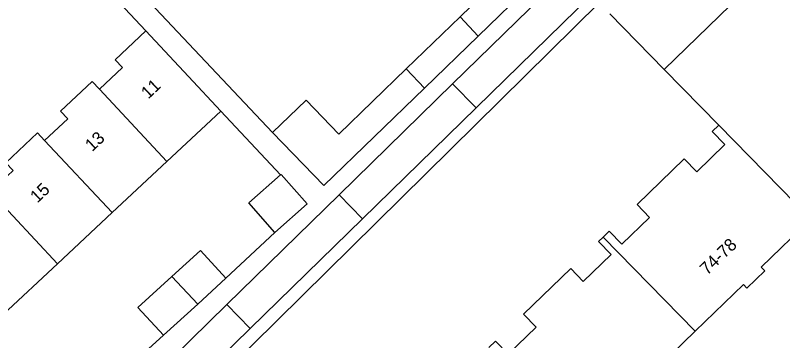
# Model space of a CAD drawing. Extents: x 161882 to 162509, y 381687 to 382379.
# Drawn here: x 162409.8 to 162471.3, y 381812.8 to 381838.9 of the extents above; entities that cross this region are included whole.
import ezdxf

# ---------------------------------------------------------------- set-up
doc = ezdxf.new("R2010")
doc.units = 0
for name, color, linetype in [('IMGEO_Pand', 7, 'Continuous'), ('IMGEO_Pand_nummerreeks', 7, 'Continuous'), ('IMGEO_Rijbaan_lokaal_open', 7, 'Continuous'), ('IMGEO_Voetpad_open', 7, 'Continuous')]:
    doc.layers.add(name, color=color, linetype=linetype)

msp = doc.modelspace()

# ---------------------------------------------------------------- linework, layer by layer
at = {"layer": 'IMGEO_Pand'}
for points in [[(162461.809, 381834.525), (162468.874, 381841.412), (162472.454, 381844.902), (162474.369, 381842.947)], [(162445.46, 381838.744), (162449.764, 381842.916)], [(162444.862, 381833.372), (162454.078, 381842.393), (162455.959, 381840.477), (162446.742, 381831.455)], [(162451.213, 381841.37), (162446.909, 381837.198)], [(162441.156, 381834.572), (162445.46, 381838.744)], [(162446.909, 381837.198), (162445.46, 381838.744)], [(162416.575, 381832.94), (162418.422, 381834.667), (162417.831, 381835.299), (162420.305, 381837.611)], [(162426.31, 381831.186), (162423.719, 381833.958), (162420.305, 381837.611)], [(162446.909, 381837.198), (162442.605, 381833.026)], [(162430.442, 381829.459), (162433.129, 381832.063), (162435.763, 381829.345), (162441.156, 381834.572)], [(162441.156, 381834.572), (162442.605, 381833.026)], [(162461.809, 381834.525), (162466.185, 381830.057)], [(162412.188, 381828.836), (162414.043, 381830.57), (162413.465, 381831.188), (162415.999, 381833.556), (162416.575, 381832.94)], [(162435.772, 381824.472), (162444.862, 381833.372)], [(162444.862, 381833.372), (162446.742, 381831.455)], [(162416.575, 381832.94), (162421.988, 381827.147)], [(162442.605, 381833.026), (162434.551, 381825.22), (162430.442, 381829.459)], [(162446.742, 381831.455), (162437.651, 381822.555)], [(162426.31, 381831.186), (162421.988, 381827.147)], [(162466.185, 381830.057), (162465.65, 381829.539), (162466.659, 381828.498), (162464.418, 381826.327), (162463.409, 381827.368), (162459.63, 381823.708), (162460.639, 381822.667), (162458.413, 381820.511), (162457.404, 381821.552), (162456.915, 381821.079)], [(162473.56, 381822.527), (162466.185, 381830.057)], [(162412.188, 381828.836), (162411.632, 381829.429), (162409.083, 381827.047), (162409.665, 381826.424), (162407.83, 381824.709)], [(162417.6, 381823.046), (162412.188, 381828.836)], [(162421.988, 381827.147), (162417.6, 381823.046)], [(162430.632, 381821.461), (162428.548, 381823.828), (162431.094, 381826.068)], [(162431.094, 381826.068), (162431.145, 381826.113), (162433.228, 381823.746), (162430.632, 381821.461)], [(162407.83, 381824.709), (162413.215, 381818.948)], [(162426.783, 381815.673), (162435.772, 381824.472)], [(162437.651, 381822.555), (162435.772, 381824.472)], [(162413.215, 381818.948), (162417.6, 381823.046)], [(162437.651, 381822.555), (162428.663, 381813.756)], [(162464.294, 381813.553), (162468.154, 381817.292), (162468.433, 381817.005), (162469.863, 381818.389), (162469.584, 381818.676), (162473.56, 381822.527)], [(162456.915, 381821.079), (162456.549, 381820.724), (162457.558, 381819.683), (162455.331, 381817.526), (162454.322, 381818.567), (162450.544, 381814.907), (162451.553, 381813.866), (162449.319, 381811.703), (162448.31, 381812.744), (162447.776, 381812.227)], [(162456.915, 381821.079), (162464.294, 381813.553)], [(162422.384, 381817.928), (162424.674, 381820.019), (162426.715, 381817.784)], [(162413.215, 381818.948), (162408.862, 381814.879)], [(162421.709, 381813.214), (162419.669, 381815.448), (162422.384, 381817.928)], [(162422.384, 381817.928), (162424.451, 381815.717)], [(162426.715, 381817.784), (162424.451, 381815.717)], [(162408.087, 381797.371), (162426.783, 381815.673)], [(162424.451, 381815.717), (162421.709, 381813.214)], [(162426.783, 381815.673), (162428.663, 381813.756)], [(162428.663, 381813.756), (162409.777, 381795.269)], [(162455.154, 381804.701), (162458.924, 381808.352), (162459.203, 381808.065), (162460.711, 381809.526), (162460.432, 381809.813), (162464.294, 381813.553)]]:
    msp.add_lwpolyline(points, dxfattribs=at)
at = {"layer": 'IMGEO_Rijbaan_lokaal_open'}
msp.add_lwpolyline([(162457.462, 381838.965), (162461.809, 381834.525)], dxfattribs=at)
at = {"layer": 'IMGEO_Voetpad_open'}
for points in [[(162430.442, 381829.459), (162415.713, 381845.109)], [(162420.305, 381837.611), (162414.428, 381843.9)], [(162429.518, 381794.561), (162421.052, 381804.384), (162420.873, 381804.592), (162456.614, 381839.875)], [(162431.094, 381826.068), (162426.31, 381831.186)], [(162426.715, 381817.784), (162430.632, 381821.461)], [(162417.855, 381809.694), (162421.709, 381813.214)]]:
    msp.add_lwpolyline(points, dxfattribs=at)

# ---------------------------------------------------------------- texts
at = {"layer": 'IMGEO_Pand_nummerreeks'}
for s, rotation, p in [('11', 43.16091, (162420.486, 381832.099)), ('13', 43.16091, (162416.004, 381827.895)), ('15', 43.16091, (162411.605, 381823.77)), ('74-78', 44.08135, (162465.251, 381817.988))]:
    msp.add_text(s, height=1, rotation=rotation, dxfattribs=at).set_placement(p)

doc.saveas('drawing.dxf')
